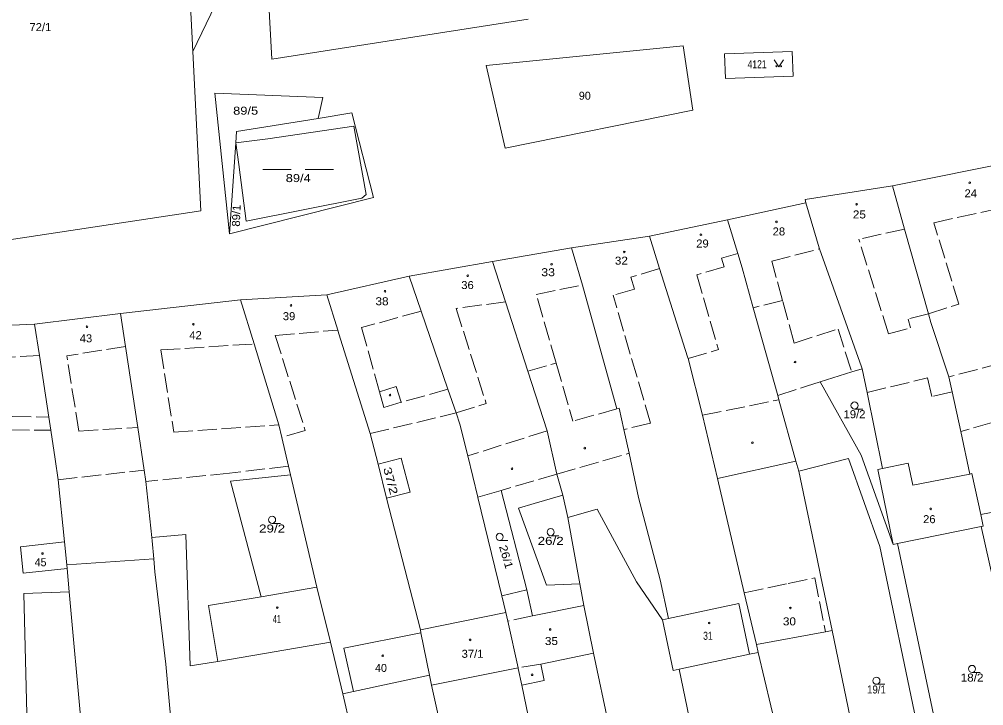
# Model space of a CAD drawing. Extents: x -590528 to -586543, y -1119609 to -1116685.
# Drawn here: x -589035.6 to -588830.7, y -1118676.3 to -1118530.4 of the extents above; entities that cross this region are included whole.
import ezdxf
from ezdxf.enums import TextEntityAlignment as Align

# ---------------------------------------------------------------- set-up
doc = ezdxf.new("R2010")
doc.units = 0
doc.header["$LTSCALE"] = 0.68
doc.linetypes.add('LONG_DASHED', pattern=[7.5, 6, -1.5])
for name, color, linetype, lineweight in [('1', 7, 'Continuous', 13), ('2', 7, 'LONG_DASHED', 13), ('3', 7, 'Continuous', 13), ('6', 7, 'Continuous', 13)]:
    doc.layers.add(name, color=color, linetype=linetype, lineweight=lineweight)

msp = doc.modelspace()

# ---------------------------------------------------------------- hatches: boundary and pattern name
at = {"layer": '6'}
for points in [[(-588874.66, -1118540.44, 1), (-588874.86, -1118540.44, 1)], [(-588873.66, -1118540.44, 1), (-588873.86, -1118540.44, 1)]]:
    msp.add_hatch(color=256, dxfattribs=at).paths.add_polyline_path(points)

# ---------------------------------------------------------------- linework, layer by layer
at = {"layer": '1'}
for p, q in [((-588981.96, -1118538.9), (-588985.18, -1118478.05)), ((-588981.96, -1118538.9), (-588927.52, -1118530.39)), ((-588885.81, -1118537.78), (-588871.43, -1118537.26)), ((-588885.81, -1118537.78), (-588885.61, -1118543.06)), ((-588871.43, -1118537.26), (-588871.19, -1118542.54)), ((-588885.61, -1118543.06), (-588871.19, -1118542.54)), ((-588971.15, -1118547.09), (-588972.14, -1118551.5)), ((-588964.93, -1118550.33), (-588960.35, -1118568.3)), ((-588850.12, -1118565.82), (-588868.69, -1118568.75)), ((-588960.35, -1118568.3), (-588990.94, -1118576.07)), ((-588868.48, -1118569.45), (-588885.19, -1118573.08)), ((-589049.99, -1118579.12), (-588997.04, -1118571.17)), ((-588885.19, -1118573.08), (-588901.76, -1118576.53)), ((-588901.76, -1118576.53), (-588918.31, -1118579.03)), ((-588918.31, -1118579.03), (-588935.06, -1118581.92)), ((-588918.31, -1118579.03), (-588915.98, -1118586.91)), ((-588865.68, -1118579), (-588865.61, -1118579.23)), ((-588865.61, -1118579.23), (-588856.68, -1118604.26)), ((-588882.03, -1118583.25), (-588879.72, -1118591.73)), ((-588908.67, -1118613.2), (-588915.98, -1118586.91)), ((-589014.11, -1118592.95), (-588988.59, -1118590.04)), ((-588988.59, -1118590.04), (-588970.29, -1118588.97)), ((-588988.59, -1118590.04), (-588985.74, -1118599.42)), ((-588879.72, -1118591.73), (-588874.48, -1118610.38)), ((-589013.05, -1118599.97), (-589014.11, -1118592.95)), ((-589032.38, -1118595.2), (-589031.35, -1118601.89)), ((-588841.95, -1118594.88), (-588838.1, -1118606.42)), ((-588961.05, -1118618.46), (-588967.7, -1118597.31)), ((-589010.46, -1118617.2), (-589013.05, -1118599.97)), ((-588893.63, -1118602.18), (-588893.54, -1118602.52)), ((-588890.47, -1118614.59), (-588893.54, -1118602.52)), ((-588927.56, -1118605.23), (-588923.48, -1118617.89)), ((-588865.44, -1118607.48), (-588858.77, -1118605.34)), ((-588858.77, -1118605.34), (-588856.58, -1118604.72)), ((-588865.44, -1118607.48), (-588856.77, -1118623.07)), ((-588944.55, -1118609.06), (-588942.82, -1118614.1)), ((-588855.45, -1118609.75), (-588852.21, -1118625.89)), ((-588908.18, -1118613.09), (-588908.67, -1118613.2)), ((-588890.47, -1118614.59), (-588887.31, -1118628.02)), ((-589028.94, -1118617.74), (-589028, -1118623.9)), ((-588921.41, -1118627.07), (-588923.48, -1118617.89)), ((-588835.6, -1118618.01), (-588833.64, -1118627.08)), ((-588906.04, -1118622.65), (-588904.04, -1118632.04)), ((-589028, -1118623.9), (-589027.37, -1118628.29)), ((-588959.4, -1118624.97), (-588954.45, -1118623.7)), ((-588954.45, -1118623.7), (-588952.6, -1118630.9)), ((-588887.31, -1118628.02), (-588870.61, -1118624.35)), ((-588859.48, -1118623.8), (-588870.02, -1118626.47)), ((-588852.79, -1118642.5), (-588859.48, -1118623.8)), ((-588856.77, -1118623.07), (-588849.96, -1118642.02)), ((-588978, -1118627.26), (-588978.39, -1118625.38)), ((-588852.21, -1118625.89), (-588853.21, -1118626.12)), ((-588853.21, -1118626.12), (-588849.96, -1118642.02)), ((-588833.22, -1118626.99), (-588833.64, -1118627.08)), ((-588978, -1118627.26), (-588990.71, -1118628.58)), ((-588990.71, -1118628.58), (-588984.24, -1118653.13)), ((-588978, -1118627.26), (-588972.42, -1118651.12)), ((-588921.41, -1118627.07), (-588920.12, -1118631.59)), ((-588887.31, -1118628.02), (-588881.59, -1118652.3)), ((-588957.58, -1118632.18), (-588952.6, -1118630.9)), ((-588933.27, -1118630.57), (-588938.19, -1118631.97)), ((-588933.27, -1118630.57), (-588927.79, -1118651.68)), ((-588938.17, -1118632.07), (-588933.13, -1118652.97)), ((-588926.23, -1118633.33), (-588920.12, -1118631.59)), ((-588920.12, -1118631.59), (-588919.08, -1118636.28)), ((-588904.04, -1118632.04), (-588899.49, -1118649.55)), ((-588831.35, -1118635.65), (-588811.61, -1118631.91)), ((-588919.08, -1118636.28), (-588912.82, -1118634.52)), ((-588912.82, -1118634.52), (-588904.46, -1118650.01)), ((-588919.08, -1118636.28), (-588916.54, -1118650.43)), ((-588823.66, -1118672.27), (-588831.29, -1118638.24)), ((-589007.43, -1118640.53), (-589000.2, -1118639.91)), ((-589000.2, -1118639.91), (-588999.32, -1118667.83)), ((-589026.01, -1118641.51), (-589035.38, -1118642.53)), ((-589035.38, -1118642.53), (-589034.78, -1118648.16)), ((-588837.53, -1118715.66), (-588852.79, -1118642.5)), ((-588833.75, -1118714.49), (-588849.05, -1118641.84)), ((-589025.5, -1118646.34), (-589007.03, -1118645.08)), ((-589025.43, -1118647.15), (-589034.78, -1118648.16)), ((-589006.8, -1118647.85), (-589004.49, -1118667.45)), ((-588899.49, -1118649.55), (-588897.72, -1118657.8)), ((-588865.34, -1118648.89), (-588862.94, -1118660.35)), ((-588972.42, -1118651.12), (-588969.47, -1118662.8)), ((-588923.64, -1118650.7), (-588916.54, -1118650.43)), ((-588916.54, -1118650.43), (-588915.71, -1118655.01)), ((-588904.46, -1118650.01), (-588898.99, -1118658.07)), ((-589024.98, -1118652.09), (-589034.66, -1118652.43)), ((-589033.39, -1118702.35), (-589034.66, -1118652.43)), ((-589024.98, -1118652.09), (-589020.6, -1118700.74)), ((-588927.79, -1118651.68), (-588933.13, -1118652.97)), ((-588926.55, -1118657.22), (-588927.79, -1118651.68)), ((-588881.59, -1118652.3), (-588879.01, -1118663.27)), ((-588993.4, -1118666.88), (-588995.42, -1118655.04)), ((-588926.55, -1118657.22), (-588915.71, -1118655.01)), ((-588915.71, -1118655.01), (-588913.64, -1118665.15)), ((-588882.76, -1118654.59), (-588897.72, -1118657.8)), ((-588880.45, -1118665.34), (-588882.76, -1118654.59)), ((-588898.99, -1118658.07), (-588897.72, -1118657.8)), ((-588896.68, -1118668.82), (-588898.99, -1118658.07)), ((-588950.27, -1118660.84), (-588966.69, -1118664.05)), ((-588862.94, -1118660.35), (-588850.59, -1118719.87)), ((-588969.47, -1118662.8), (-588993.4, -1118666.88)), ((-588966.85, -1118673.77), (-588969.47, -1118662.8)), ((-588966.69, -1118664.05), (-588964.58, -1118673.29)), ((-588913.64, -1118665.15), (-588924.8, -1118667.44)), ((-588913.64, -1118665.15), (-588898.21, -1118737.82)), ((-588895.41, -1118668.55), (-588880.45, -1118665.34)), ((-588880.45, -1118665.34), (-588878.61, -1118664.98)), ((-589004.49, -1118667.45), (-588998.7, -1118730.71)), ((-588993.4, -1118666.88), (-588999.32, -1118667.83)), ((-588924.8, -1118667.44), (-588924.08, -1118670.97)), ((-588948.44, -1118669.84), (-588948.01, -1118671.96)), ((-588929.65, -1118668.22), (-588948.01, -1118671.96)), ((-588929.6, -1118668.42), (-588928.88, -1118671.95)), ((-588896.68, -1118668.82), (-588895.41, -1118668.55)), ((-588895.41, -1118668.55), (-588881.9, -1118733.34)), ((-588948.01, -1118671.96), (-588931.82, -1118744.38)), ((-588924.08, -1118670.97), (-588928.88, -1118671.95)), ((-588928.88, -1118671.95), (-588914.12, -1118741.94)), ((-588966.85, -1118673.77), (-588951.59, -1118740.78))]:
    msp.add_line(p, q, dxfattribs=at)
for points in [[(-588997.04, -1118571.17), (-588998.77, -1118537.29), (-589000.68, -1118499.71)], [(-588995.26, -1118502.62), (-588993.99, -1118527.48), (-588998.77, -1118537.29)], [(-588990.94, -1118576.07), (-588994.07, -1118546.15), (-588971.15, -1118547.09)], [(-588989.45, -1118554.31), (-588972.14, -1118551.5), (-588964.93, -1118550.33)], [(-588987.41, -1118573.33), (-588989, -1118561.32), (-588989.61, -1118556.72), (-588982.8, -1118555.84), (-588964.57, -1118553.13), (-588961.94, -1118567.7)], [(-588990.94, -1118576.07), (-588989.61, -1118556.72), (-588989.45, -1118554.31)], [(-588823.59, -1118560.51), (-588850.12, -1118565.82), (-588847.53, -1118575.03)], [(-588987.41, -1118573.33), (-588962.85, -1118568.49), (-588961.94, -1118567.7)], [(-588868.69, -1118568.75), (-588868.48, -1118569.45), (-588865.68, -1118579)], [(-588885.19, -1118573.08), (-588882.98, -1118580.19), (-588882.03, -1118583.25)], [(-588847.53, -1118575.03), (-588842.48, -1118593), (-588841.95, -1118594.88)], [(-588901.76, -1118576.53), (-588899.57, -1118583.43), (-588893.63, -1118602.18)], [(-588970.29, -1118588.97), (-588952.78, -1118585.06), (-588935.06, -1118581.92)], [(-588935.06, -1118581.92), (-588932.3, -1118590.49), (-588927.56, -1118605.23)], [(-588952.78, -1118585.06), (-588950.25, -1118592.45), (-588944.55, -1118609.06)], [(-588970.29, -1118588.97), (-588967.96, -1118596.47), (-588967.7, -1118597.31)], [(-589014.11, -1118592.95), (-589032.38, -1118595.2), (-589053.23, -1118596.15)], [(-588985.74, -1118599.42), (-588980.44, -1118616.62), (-588979.82, -1118619.29), (-588978.39, -1118625.38)], [(-589031.35, -1118601.89), (-589029.36, -1118614.97), (-589028.94, -1118617.74)], [(-588856.68, -1118604.26), (-588856.58, -1118604.72), (-588855.45, -1118609.75)], [(-588838.1, -1118606.42), (-588837.42, -1118609.58), (-588835.6, -1118618.01)], [(-588874.48, -1118610.38), (-588874.23, -1118611.3), (-588870.61, -1118624.35), (-588870.02, -1118626.47)], [(-588942.82, -1118614.1), (-588941.99, -1118616.51), (-588940.29, -1118623.22)], [(-588906.04, -1118622.65), (-588907.17, -1118617.6), (-588908.18, -1118613.09)], [(-589008.73, -1118628.65), (-589009.09, -1118626.24), (-589010.46, -1118617.2)], [(-588961.05, -1118618.46), (-588959.4, -1118624.97), (-588957.58, -1118632.18), (-588950.4, -1118660.2)], [(-588940.29, -1118623.22), (-588938.19, -1118631.97), (-588938.17, -1118632.07)], [(-588833.64, -1118627.08), (-588845.75, -1118629.47), (-588846.76, -1118624.77), (-588852.21, -1118625.89)], [(-588870.02, -1118626.47), (-588866.21, -1118644.72), (-588865.34, -1118648.89)], [(-588831.29, -1118638.24), (-588830.81, -1118638.14), (-588831.35, -1118635.65), (-588833.22, -1118626.99)], [(-589027.37, -1118628.29), (-589026.01, -1118641.51), (-589025.5, -1118646.34)], [(-589008.73, -1118628.65), (-589007.43, -1118640.53), (-589007.35, -1118641.27), (-589007.03, -1118645.08), (-589006.8, -1118647.85)], [(-588926.23, -1118633.33), (-588929.56, -1118634.33), (-588923.64, -1118650.7)], [(-588831.29, -1118638.24), (-588849.05, -1118641.84), (-588849.96, -1118642.02)], [(-589025.5, -1118646.34), (-589025.43, -1118647.15), (-589024.98, -1118652.09)], [(-588972.42, -1118651.12), (-588984.24, -1118653.13), (-588995.42, -1118655.04)], [(-588931.84, -1118658.32), (-588932.28, -1118656.51), (-588933.13, -1118652.97)], [(-588932.28, -1118656.51), (-588950.4, -1118660.2), (-588950.27, -1118660.84), (-588948.44, -1118669.84)], [(-588931.84, -1118658.32), (-588929.65, -1118668.22), (-588929.6, -1118668.42)], [(-588879.01, -1118663.27), (-588864.37, -1118660.61), (-588862.94, -1118660.35)], [(-588879.01, -1118663.27), (-588878.61, -1118664.98), (-588871.93, -1118693.33)], [(-588948.44, -1118669.84), (-588964.58, -1118673.29), (-588966.85, -1118673.77)]]:
    msp.add_lwpolyline(points, dxfattribs=at)
msp.add_lwpolyline([(-588936.4, -1118540.24), (-588894.58, -1118536.1), (-588892.51, -1118549.76), (-588932.41, -1118557.82)], close=True, dxfattribs=at)
at = {"layer": '2'}
for p, q in [((-588836.02, -1118590.95), (-588841.33, -1118573.67)), ((-588847.53, -1118575.03), (-588857.26, -1118577.16)), ((-588850.96, -1118597.28), (-588857.26, -1118577.16)), ((-588882.98, -1118580.19), (-588886.41, -1118581.2)), ((-588886.41, -1118581.2), (-588885.87, -1118583.05)), ((-588899.57, -1118583.43), (-588905.68, -1118585.22)), ((-588905.68, -1118585.22), (-588904.94, -1118587.77)), ((-588904.94, -1118587.77), (-588909.46, -1118589.1)), ((-588901.51, -1118616.26), (-588909.46, -1118589.1)), ((-588932.3, -1118590.49), (-588942.79, -1118591.87)), ((-588942.79, -1118591.87), (-588936.42, -1118612.09)), ((-588842.48, -1118593), (-588836.02, -1118590.95)), ((-588842.48, -1118593), (-588846.78, -1118594.14)), ((-588846.28, -1118596.03), (-588846.78, -1118594.14)), ((-588850.96, -1118597.28), (-588846.28, -1118596.03)), ((-588981.22, -1118597.64), (-588967.96, -1118596.47)), ((-588981.22, -1118597.64), (-588974.86, -1118617.83)), ((-589013.05, -1118599.97), (-589025.52, -1118601.97)), ((-589005.51, -1118600.7), (-588985.74, -1118599.42)), ((-588807.37, -1118598.35), (-588838.1, -1118606.42)), ((-589031.35, -1118601.89), (-589047.94, -1118602.71)), ((-589022.96, -1118617.93), (-589025.52, -1118601.97)), ((-588893.54, -1118602.52), (-588887.05, -1118600.61)), ((-588927.56, -1118605.23), (-588921.55, -1118603.52)), ((-588921.55, -1118603.52), (-588918.03, -1118615.87)), ((-588959.09, -1118609.59), (-588955.52, -1118608.49)), ((-588954.49, -1118611.83), (-588955.52, -1118608.49)), ((-588874.48, -1118610.38), (-588868.39, -1118608.43)), ((-588868.39, -1118608.43), (-588865.44, -1118607.48)), ((-588855.45, -1118609.75), (-588842.69, -1118606.66)), ((-588842.69, -1118606.66), (-588841.73, -1118610.62)), ((-588959.09, -1118609.59), (-588958.17, -1118612.91)), ((-588944.55, -1118609.06), (-588954.49, -1118611.83)), ((-588837.42, -1118609.58), (-588841.73, -1118610.62)), ((-588804.37, -1118609.31), (-588835.6, -1118618.01)), ((-588954.49, -1118611.83), (-588958.17, -1118612.91)), ((-588942.82, -1118614.1), (-588936.42, -1118612.09)), ((-588890.47, -1118614.59), (-588874.23, -1118611.3)), ((-589047.35, -1118614.61), (-589029.36, -1118614.97)), ((-588961.05, -1118618.46), (-588942.82, -1118614.1)), ((-588908.67, -1118613.2), (-588918.03, -1118615.87)), ((-588901.51, -1118616.26), (-588907.17, -1118617.6)), ((-589022.96, -1118617.93), (-589010.46, -1118617.2)), ((-588974.86, -1118617.83), (-588979.82, -1118619.29)), ((-588923.48, -1118617.89), (-588940.29, -1118623.22)), ((-588921.41, -1118627.07), (-588906.04, -1118622.65)), ((-589027.37, -1118628.29), (-589009.09, -1118626.24)), ((-588921.41, -1118627.07), (-588933.27, -1118630.57)), ((-588926.55, -1118657.22), (-588931.84, -1118658.32)), ((-588924.8, -1118667.44), (-588929.65, -1118668.22))]:
    msp.add_line(p, q, dxfattribs=at)
for points in [[(-588841.33, -1118573.67), (-588827.56, -1118570.65), (-588822.92, -1118586.48)], [(-588873.47, -1118590.2), (-588875.77, -1118581.83), (-588865.61, -1118579.23)], [(-588885.87, -1118583.05), (-588891.7, -1118584.77), (-588887.05, -1118600.61)], [(-588921.55, -1118603.52), (-588925.79, -1118588.92), (-588915.98, -1118586.91)], [(-588871.02, -1118599.25), (-588873.47, -1118590.2), (-588879.72, -1118591.73)], [(-588950.25, -1118592.45), (-588962.89, -1118595.97), (-588959.09, -1118609.59)], [(-588871.02, -1118599.25), (-588861.68, -1118596.26), (-588858.77, -1118605.34)], [(-589005.51, -1118600.7), (-589002.8, -1118618.19), (-588980.44, -1118616.62)], [(-589042.69, -1118617.68), (-589037.54, -1118617.7), (-589028.94, -1118617.74)], [(-588978.39, -1118625.38), (-588990.93, -1118626.88), (-589008.73, -1118628.65)], [(-588881.59, -1118652.3), (-588872.26, -1118650.34), (-588866.6, -1118649.16), (-588864.37, -1118660.61)]]:
    msp.add_lwpolyline(points, dxfattribs=at)
at = {"layer": '6'}
for p, q in [((-588983.85, -1118562.34), (-588977.85, -1118562.34)), ((-588974.85, -1118562.34), (-588968.85, -1118562.34)), ((-588858.17, -1118613.26), (-588856.42, -1118613.26)), ((-588981.9, -1118637.55), (-588980.15, -1118637.55)), ((-588933.57, -1118641.17), (-588931.82, -1118641.17)), ((-588922.72, -1118640.17), (-588920.97, -1118640.17)), ((-588833.2, -1118669.22), (-588831.45, -1118669.22)), ((-588853.51, -1118671.75), (-588851.76, -1118671.75))]:
    msp.add_line(p, q, dxfattribs=at)
msp.add_lwpolyline([(-588875.26, -1118539.04), (-588874.26, -1118540.54), (-588873.26, -1118539.04)], dxfattribs=at)
for centre, radius in [((-588874.76, -1118540.44), 0.1), ((-588873.76, -1118540.44), 0.1), ((-588833.6802, -1118565.1804), 0.175), ((-588857.7302, -1118569.7604), 0.175), ((-588874.7502, -1118573.4904), 0.175), ((-588890.8102, -1118576.2304), 0.175), ((-588907.0802, -1118579.8904), 0.175), ((-588922.5302, -1118582.5004), 0.175), ((-588940.3502, -1118584.9504), 0.175), ((-588957.9102, -1118588.2204), 0.175), ((-588977.8802, -1118591.2504), 0.175), ((-589021.2402, -1118595.7904), 0.175), ((-588998.6302, -1118595.2504), 0.175), ((-588870.7902, -1118603.2804), 0.175), ((-588956.8502, -1118610.3104), 0.175), ((-588858.17, -1118612.51), 0.75), ((-588879.8602, -1118620.4204), 0.175), ((-588915.4702, -1118621.5604), 0.175), ((-588930.9302, -1118625.9504), 0.175), ((-588841.9802, -1118634.4804), 0.175), ((-588981.9, -1118636.8), 0.75), ((-588922.72, -1118639.42), 0.75), ((-588933.57, -1118640.42), 0.75), ((-589030.6802, -1118643.9704), 0.175), ((-588980.7902, -1118655.4504), 0.175), ((-588871.7902, -1118655.5204), 0.175), ((-588889.0502, -1118658.7404), 0.175), ((-588922.8302, -1118660.1004), 0.175), ((-588939.8402, -1118662.3104), 0.175), ((-588958.4002, -1118665.6704), 0.175), ((-588833.2, -1118668.47), 0.75), ((-588926.6602, -1118669.7304), 0.175), ((-588853.51, -1118671), 0.75)]:
    msp.add_circle(centre, radius, dxfattribs=at)

# ---------------------------------------------------------------- texts
at = {"layer": '3'}
for s, width, p in [('72/1', 1.05, (-589031.13, -1118532.96)), ('4121', 0.8, (-588878.87, -1118540.86)), ('89/5', 1.2, (-588987.52, -1118550.72)), ('89/4', 1.2, (-588976.3505, -1118565.04)), ('24', 1.05, (-588833.481, -1118568.28)), ('25', 1.1, (-588857.14, -1118572.77)), ('28', 1.05, (-588874.2405, -1118576.38)), ('29', 1.05, (-588890.471, -1118578.94)), ('32', 1.1, (-588907.7005, -1118582.58)), ('33', 1.15, (-588923.2605, -1118585.04)), ('36', 1.05, (-588940.3905, -1118587.77)), ('38', 1.1, (-588958.55, -1118591.21)), ('39', 1.05, (-588978.3005, -1118594.38)), ('43', 1.05, (-589021.4505, -1118599.09)), ('42', 1.05, (-588998.171, -1118598.42)), ('19/2', 1.05, (-588858.17, -1118615.21)), ('26', 1.05, (-588842.281, -1118637.51)), ('29/2', 1.25, (-588981.9, -1118639.5)), ('26/2', 1.25, (-588922.72, -1118642.12)), ('41', 0.7, (-588980.8905, -1118658.75)), ('30', 1.1, (-588872.0005, -1118659.23)), ('35', 1.1, (-588922.5605, -1118663.4)), ('31', 0.8, (-588889.3205, -1118662.29)), ('37/1', 1.05, (-588939.3205, -1118666.12)), ('18/2', 1.1, (-588833.2, -1118671.17)), ('19/1', 0.9, (-588853.5105, -1118673.7))]:
    msp.add_text(s, height=1.7, dxfattribs=dict(at, width=width)).set_placement(p, align=Align.CENTER)
for s, p in [('90', (-588915.4705, -1118547.54)), ('45', (-589031.0905, -1118646.67)), ('40', (-588958.7705, -1118669.12))]:
    msp.add_text(s, height=1.7, dxfattribs=at).set_placement(p, align=Align.CENTER)
for s, rotation, width, p in [('89/1', 87.72, 1.05, (-588988.6693, -1118572.2153)), ('37/2', 284.932, 1.35, (-588957.5416, -1118628.7385)), ('26/1', 286.422, 1.15, (-588932.9893, -1118644.8992))]:
    msp.add_text(s, height=1.7, rotation=rotation, dxfattribs=dict(at, width=width)).set_placement(p, align=Align.CENTER)

doc.saveas('drawing.dxf')
